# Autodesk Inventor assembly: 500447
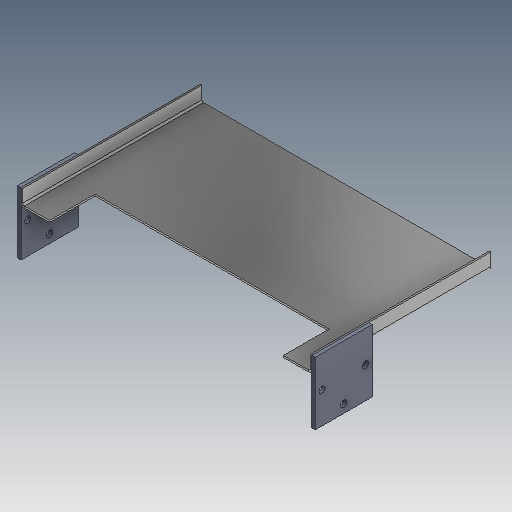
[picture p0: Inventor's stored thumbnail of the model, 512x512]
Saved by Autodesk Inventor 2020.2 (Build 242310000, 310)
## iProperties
Created: 2000-01
Part Number: 500447
Description: WMT-CP,SS,XX,BUCKET_BOTTOM,BACK _SIDE
Document SubType Name: Assembly
Designer: glanglot
Mass: 182.199 g
Surface Area: 845.613 cm^2
Volume: 69.2104 cm^3
Density: 2.63254 g/cm^3
Control State: 0
Checked Out: False
Master: False
Shininess: 0.0
Length Units: 11269
Angle Units: 11279
Time Units: 11290
Mass Units: 11283
Length Display Precision: 3
Angle Display Precision: 2
Compacted: True
Dimensions: 55x157x260,8 mm
Mass: 0,182 kg
Density: 0.0
Volumn: 0.0
Area: 0.0
PropertySet Name: Model Information
Author: glanglot
Revision Number: -
Title: WMT-CP,SS,XX,BUCKET_BOTTOM,BACK _SIDE
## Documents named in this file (3)
- D:\07 - DEMODATEN\OTX 2019 - Dataset - UPDATE - Dez2019\Designs\07-Packing machine\500447.iam
- D:\07 - DEMODATEN\OTX 2019 - Dataset - UPDATE - Dez2019\Designs\07-Packing machine\Parts\ADSK-011403.ipt
- D:\07 - DEMODATEN\OTX 2019 - Dataset - UPDATE - Dez2019\Designs\07-Packing machine\Parts\ADSK-011404.ipt
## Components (3 placed, 2 different names)
1. ADSK-011403:1 — Passend:1, Passend:2, Fluchtend:1, Fluchtend:2, Fluchtend:4
2. ADSK-011404:1 — Passend:1, Fluchtend:1, Fluchtend:3, Fluchtend:4
3. ADSK-011404:2 — Passend:2, Fluchtend:2, Fluchtend:3
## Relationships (6: Flush 4, Mate 2)
- Passend:1 [Mate]: ADSK-011403:1 ↔ ADSK-011404:1
- Passend:2 [Mate]: ADSK-011403:1 ↔ ADSK-011404:2
- Fluchtend:1 [Flush]: ADSK-011403:1 ↔ ADSK-011404:1
- Fluchtend:2 [Flush]: ADSK-011403:1 ↔ ADSK-011404:2
- Fluchtend:3 [Flush]: ADSK-011404:1 ↔ ADSK-011404:2
- Fluchtend:4 [Flush]: ADSK-011403:1 ↔ ADSK-011404:1
